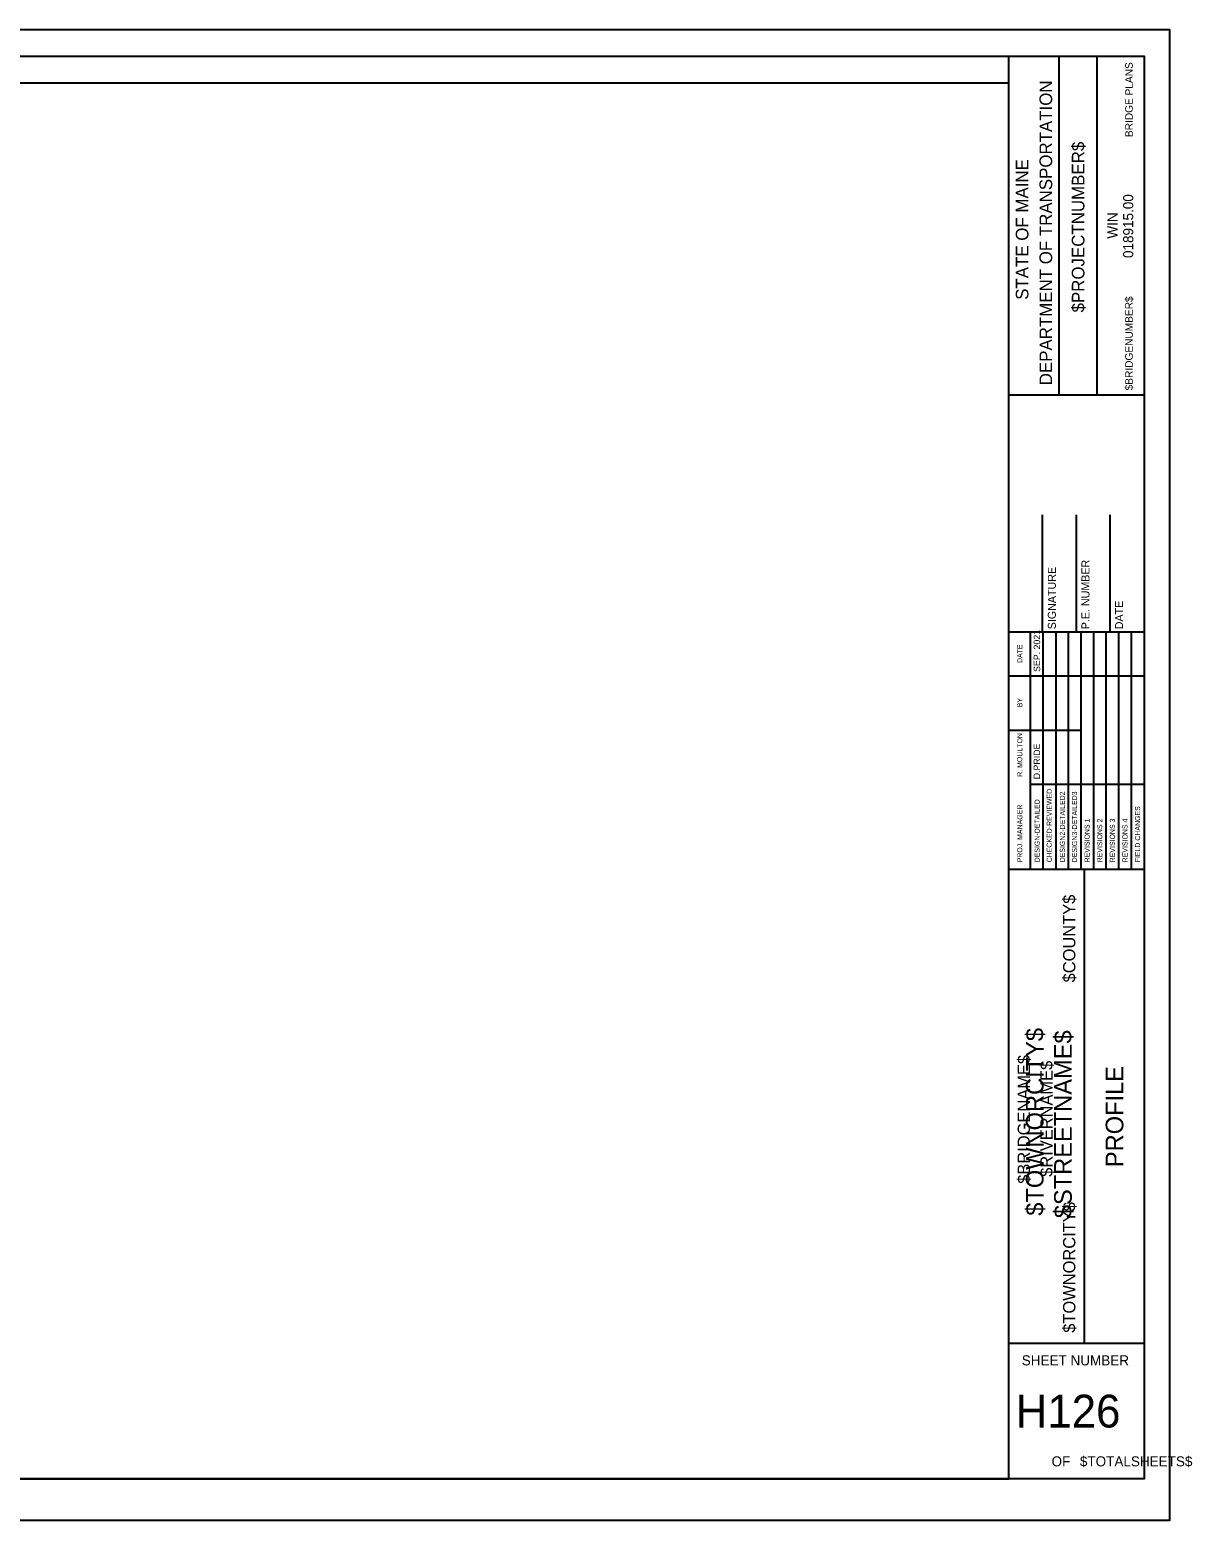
# Model space of a CAD drawing. Extents: x 10878 to 11736, y 9985 to 10535.
# Drawn here: x 11307 to 11736, y 9985 to 10535 of the extents above; entities that cross this region are included whole.
import ezdxf

# ---------------------------------------------------------------- set-up
doc = ezdxf.new("R2010")
doc.units = 0
for name, color, linetype in [('BORDER', 7, 'Continuous'), ('BRIDGE_TITLE', 7, 'Continuous'), ('CLIPS', 7, 'Continuous'), ('HIGHWAY_TITLE', 7, 'Continuous'), ('PLOT BOUNDARY', 7, 'Continuous')]:
    doc.layers.add(name, color=color, linetype=linetype)

msp = doc.modelspace()

# ---------------------------------------------------------------- linework, layer by layer
at = {"layer": 'BORDER'}
for p, q in [((11668.31, 10000), (11668.31, 10525)), ((11686.96, 10399.99), (11686.96, 10524.99)), ((11700.93, 10399.99), (11700.93, 10524.99)), ((11668.32, 10399.97), (11718.31, 10399.97)), ((11680.81, 10312.51), (11680.81, 10355.75)), ((11693.31, 10312.51), (11693.31, 10355.75)), ((11705.81, 10312.51), (11705.81, 10355.75)), ((11668.31, 10312.51), (11718.31, 10312.51)), ((11668.31, 10225.01), (11718.31, 10225.01)), ((11696.27, 10050.01), (11696.27, 10225.01)), ((11668.31, 10050.01), (11718.31, 10050.01))]:
    msp.add_line(p, q, dxfattribs=at)
msp.add_lwpolyline([(10918.31, 10525), (11718.31, 10525), (11718.31, 10000), (10918.31, 10000)], close=True, dxfattribs=at)
for points in [[(11676.39, 10296.26), (11676.39, 10312.51)], [(11681.05, 10225.03), (11681.05, 10312.51)], [(11685.71, 10312.51), (11685.71, 10225.03)], [(11690.37, 10225.03), (11690.37, 10312.51)], [(11695.03, 10225.03), (11695.03, 10312.51)], [(11699.69, 10225.03), (11699.69, 10312.51)], [(11704.34, 10225.03), (11704.34, 10312.51)], [(11709, 10225.03), (11709, 10312.51)], [(11713.66, 10225.03), (11713.66, 10312.51)], [(11676.39, 10225.03), (11676.39, 10308.98)], [(11668.31, 10296.26), (11718.31, 10296.26)], [(11668.31, 10276.26), (11676.39, 10276.26)], [(11676.39, 10276.26), (11695.02, 10276.26)], [(11676.39, 10256.26), (11718.31, 10256.26)]]:
    msp.add_lwpolyline(points, dxfattribs=at)
at = {"layer": 'CLIPS'}
msp.add_lwpolyline([(10918.31, 10000), (11668.31, 10000), (11668.31, 10515), (10918.31, 10515)], close=True, dxfattribs=at)
at = {"layer": 'PLOT BOUNDARY'}
msp.add_lwpolyline([(10877.85, 9984.7), (11727.85, 9984.7), (11727.85, 10534.7), (10877.85, 10534.7)], close=True, dxfattribs=at)

# ---------------------------------------------------------------- texts
at = {"layer": 'BORDER'}
for s, height, rotation, p in [('DEPARTMENT OF TRANSPORTATION', 4.6588, 90, (11684.35, 10403.53)), ('$PROJECTNUMBER$', 4.6588, 90, (11696.27, 10430.4)), ('STATE OF MAINE', 4.6588, 90, (11675.59, 10435.06)), ('018915.00', 3.726, 90, (11714.29, 10450.49)), ('WIN', 3.726, 90, (11708.5, 10457.65)), ('SIGNATURE', 2.953, 90, (11685.72, 10313.48)), ('P.E. NUMBER', 2.9528, 90, (11698.12, 10313.48)), ('DATE', 2.953, 90, (11710.52, 10313.48)), ('SEP. 2021', 2.423, 90, (11679.93, 10297.74)), ('DATE', 1.857, 90, (11673.34, 10301.04)), ('BY', 1.857, 90, (11673.34, 10284.69)), ('R. MOULTON', 1.864, 90, (11673.34, 10259.03)), ('D.PRIDE', 2.423, 90, (11679.93, 10258.13)), ('CHECKED-REVIEWED', 1.8637, 90, (11684.22, 10227.46)), ('DESIGN2-DETAILED2', 1.8637, 90, (11689.06, 10227.46)), ('DESIGN3-DETAILED3', 1.8637, 90, (11693.54, 10227.46)), ('PROJ. MANAGER', 1.8637, 90, (11673.34, 10227.46)), ('DESIGN-DETAILED', 1.8637, 90, (11679.75, 10227.46)), ('FIELD CHANGES', 1.8637, 90, (11716.83, 10227.46)), ('REVISIONS 1', 1.8637, 90, (11698.19, 10227.46)), ('REVISIONS 2', 1.8637, 90, (11702.85, 10227.46)), ('REVISIONS 3', 1.8637, 90, (11707.51, 10227.46)), ('REVISIONS 4', 1.8637, 90, (11712.17, 10227.46)), ('PROFILE', 6.521, 90, (11710.64, 10115)), ('SHEET NUMBER', 3.7264, 360, (11673.14, 10041.83)), ('H126', 12.097, 360, (11670.89, 10018.91)), ('OF', 3.726, 360, (11684.15, 10004.56)), ('$TOTALSHEETS$', 3.7264, 360, (11694.6, 10004.56))]:
    msp.add_text(s, height=height, rotation=rotation, dxfattribs=at).set_placement(p)
at = {"layer": 'BRIDGE_TITLE'}
for s, height, p in [('BRIDGE PLANS', 2.795, (11714.11, 10495.12)), ('$BRIDGENUMBER$', 2.795, (11714.11, 10401.65)), ('$COUNTY$', 4.536, (11692.92, 10183.17)), ('$BRIDGENAME$', 4.5358, (11676.15, 10108.86)), ('$RIVERNAME$', 4.5358, (11684.53, 10111.43)), ('$TOWNORCITY$', 4.5358, (11692.92, 10053.88))]:
    msp.add_text(s, height=height, rotation=90, dxfattribs=at).set_placement(p)
at = {"layer": 'HIGHWAY_TITLE'}
for s, p in [('$TOWNORCITY$', (11681.18, 10097.06)), ('$STREETNAME$', (11691.61, 10096.16))]:
    msp.add_text(s, height=6.5214, rotation=90, dxfattribs=at).set_placement(p)

doc.saveas('drawing.dxf')
